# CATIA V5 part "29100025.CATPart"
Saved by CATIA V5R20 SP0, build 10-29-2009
Part number: 29100025
Definition: NONE
Nomenclature: 29100025
Source: Unknown
Description: 29100025
Bounding box of the stored display mesh (mm): x -12.5 to 44.548, y -64 to 98.548, z -54 to 54
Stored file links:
  C:\Users\Utente\Desktop\IO LAVORO\3D X SITO CF\X SITO\PLASTICA\RF1\29100025.CATPart

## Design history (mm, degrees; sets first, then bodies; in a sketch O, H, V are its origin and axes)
Body1 "29100025" (main body)
  Solid1: solid without history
